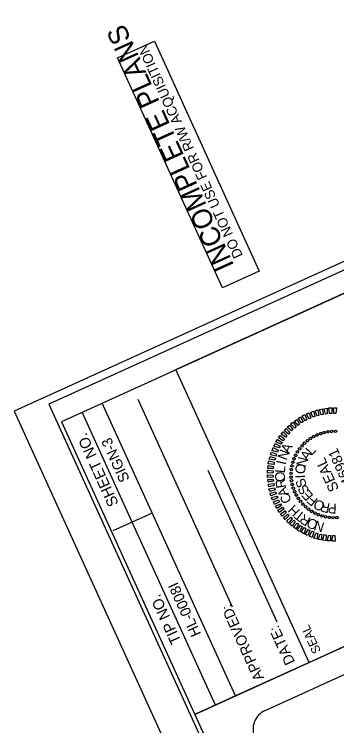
# Model space of a CAD drawing. Extents: x 2096093 to 2099001, y 683546 to 685907.
# Drawn here: x 2097306.8 to 2097494, y 685271.2 to 685684.7 of the extents above; entities that cross this region are included whole.
import ezdxf

# ---------------------------------------------------------------- set-up
doc = ezdxf.new("R2010")
doc.units = 0
for name, color, linetype in [('Default', 7, 'Continuous'), ('Old_Level_10', 7, 'Continuous'), ('Old_Level_2', 7, 'Continuous'), ('Old_Level_4', 7, 'Continuous'), ('Scratch_Level_4', 7, 'Continuous'), ('Sheet Layout Plan Border', 7, 'Continuous'), ('Sheet PE Seal Cell', 7, 'Continuous'), ('Sheet Plan CELL', 7, 'Continuous'), ('Sheet Plot Border Inside CELL', 7, 'Continuous'), ('Sheet Plot Border Outside CELL', 7, 'Continuous'), ('Sheet Sticker Incomplete CELL', 7, 'Continuous'), ('Sheet Title CELL', 7, 'Continuous')]:
    doc.layers.add(name, color=color, linetype=linetype)

msp = doc.modelspace()

# ---------------------------------------------------------------- linework, layer by layer
at = {"layer": 'Default'}
for p, q in [((2097433.54, 685340.15), (2097378.64, 685460.84)), ((2097433.54, 685340.15), (2097378.64, 685460.84)), ((2097435.15, 685288.51), (2097357.76, 685458.68)), ((2097435.15, 685288.51), (2097357.76, 685458.68)), ((2097375.24, 685389.49), (2097346.17, 685453.41)), ((2097375.24, 685389.49), (2097346.17, 685453.41)), ((2097459.39, 685331.39), (2097419.33, 685419.47)), ((2097459.39, 685331.39), (2097419.33, 685419.47)), ((2097386.83, 685394.76), (2097364.11, 685384.43)), ((2097386.83, 685394.76), (2097364.11, 685384.43)), ((2097386.83, 685394.76), (2097364.11, 685384.43)), ((2097386.83, 685394.76), (2097364.11, 685384.43)), ((2097423.56, 685283.23), (2097375.24, 685389.49)), ((2097423.56, 685283.23), (2097375.24, 685389.49)), ((2097435.15, 685288.51), (2097412.45, 685278.18)), ((2097435.15, 685288.51), (2097412.45, 685278.18))]:
    msp.add_line(p, q, dxfattribs=at)
at = {"layer": 'Old_Level_2'}
msp.add_line((2097478.08, 685308.03), (2097435.15, 685288.51), dxfattribs=at)
msp.add_line((2097478.08, 685308.03), (2097435.15, 685288.51), dxfattribs=at)
msp.add_lwpolyline([(2097478.08, 685308.03), (2097400.68, 685478.2), (2097502.07, 685524.32), (2097579.47, 685354.15)], close=True, dxfattribs=at)
msp.add_lwpolyline([(2097478.08, 685308.03), (2097400.68, 685478.2), (2097502.07, 685524.32), (2097579.47, 685354.15)], close=True, dxfattribs=at)
at = {"layer": 'Scratch_Level_4'}
msp.add_lwpolyline([(2097576.74, 685472.35), (2098256.77, 685779.32), (2098363.73, 685544.17), (2098430.06, 685574.34), (2098911.14, 684517.12), (2097955.36, 684082.39), (2097417.22, 685265.53), (2097411.63, 685277.84), (2097412.45, 685278.18), (2097621.75, 685373.38)], close=True, dxfattribs=at)
at = {"layer": 'Sheet Layout Plan Border'}
msp.add_lwpolyline([(2097576.74, 685472.35), (2098256.77, 685779.32), (2098363.73, 685544.17), (2098430.06, 685574.34), (2098911.14, 684517.12), (2097955.36, 684082.39), (2097417.22, 685265.53), (2097411.63, 685277.84), (2097412.45, 685278.18), (2097621.75, 685373.38)], close=True, dxfattribs=at)
at = {"layer": 'Sheet PE Seal Cell'}
for p, q in [((2097482.58, 685440.24), (2097482.58, 685440.24)), ((2097484.64, 685441.01), (2097484.64, 685441.01)), ((2097486.74, 685441.59), (2097486.74, 685441.59)), ((2097488.84, 685442.05), (2097488.84, 685442.05)), ((2097491.04, 685442.28), (2097491.04, 685442.28)), ((2097493.24, 685442.29), (2097493.24, 685442.29)), ((2097476.93, 685436.85), (2097476.93, 685436.85)), ((2097478.76, 685438.12), (2097478.76, 685438.12)), ((2097480.6, 685439.28), (2097480.6, 685439.28)), ((2097472.41, 685432.16), (2097472.41, 685432.16)), ((2097473.77, 685433.87), (2097473.77, 685433.87)), ((2097475.26, 685435.43), (2097475.26, 685435.43)), ((2097470.08, 685428.46), (2097470.08, 685428.46)), ((2097471.16, 685430.32), (2097471.16, 685430.32)), ((2097468.48, 685424.38), (2097468.48, 685424.38)), ((2097469.2, 685426.41), (2097469.2, 685426.41)), ((2097467.58, 685420.07), (2097467.58, 685420.07)), ((2097467.98, 685422.23), (2097467.98, 685422.23)), ((2097467.48, 685417.88), (2097467.48, 685417.88)), ((2097467.49, 685415.69), (2097467.49, 685415.69)), ((2097492.56, 685417.21), (2097492.56, 685417.21)), ((2097467.72, 685413.49), (2097467.72, 685413.49)), ((2097468.18, 685411.39), (2097468.18, 685411.39)), ((2097468.75, 685409.29), (2097468.75, 685409.29)), ((2097469.53, 685407.22), (2097469.53, 685407.22)), ((2097470.48, 685405.24), (2097470.48, 685405.24)), ((2097471.65, 685403.41), (2097471.65, 685403.41)), ((2097472.92, 685401.57), (2097472.92, 685401.57)), ((2097474.34, 685399.91), (2097474.34, 685399.91)), ((2097475.89, 685398.42), (2097475.89, 685398.42)), ((2097477.61, 685397.06), (2097477.61, 685397.06)), ((2097479.44, 685395.81), (2097479.44, 685395.81)), ((2097481.31, 685394.73), (2097481.31, 685394.73)), ((2097483.36, 685393.85), (2097483.36, 685393.85)), ((2097485.39, 685393.13), (2097485.39, 685393.13)), ((2097487.54, 685392.62), (2097487.54, 685392.62)), ((2097489.7, 685392.23), (2097489.7, 685392.23)), ((2097491.88, 685392.13), (2097491.88, 685392.13))]:
    msp.add_line(p, q, dxfattribs=at)
for points in [[(2097477.86, 685449.52), (2097476.38, 685452.42), (2097477.93, 685453.12), (2097478.96, 685450.02)], [(2097480.16, 685450.51), (2097478.9, 685453.51), (2097480.45, 685454.1), (2097481.29, 685450.92)], [(2097482.45, 685451.28), (2097481.4, 685454.31), (2097483.03, 685454.84), (2097483.64, 685451.55)], [(2097484.93, 685451.97), (2097484.01, 685454.96), (2097485.71, 685455.34), (2097486.06, 685452.04)], [(2097487.39, 685452.37), (2097486.7, 685455.46), (2097488.34, 685455.83), (2097488.51, 685452.44)], [(2097489.88, 685452.68), (2097489.42, 685455.88), (2097491.1, 685455.93), (2097491.07, 685452.61)], [(2097492.3, 685452.68), (2097492.06, 685455.98), (2097493.78, 685455.94), (2097493.51, 685452.68)], [(2097471.55, 685445.77), (2097469.38, 685448.24), (2097470.8, 685449.22), (2097472.38, 685446.48)], [(2097473.55, 685447.17), (2097471.56, 685449.84), (2097473.05, 685450.68), (2097474.56, 685447.85)], [(2097475.61, 685448.44), (2097473.9, 685451.23), (2097475.4, 685452.03), (2097476.66, 685449.03)], [(2097467.76, 685442.51), (2097465.31, 685444.75), (2097466.5, 685445.89), (2097468.51, 685443.4)], [(2097469.61, 685444.23), (2097467.24, 685446.67), (2097468.62, 685447.62), (2097470.42, 685444.98)], [(2097464.45, 685438.92), (2097461.7, 685440.74), (2097462.84, 685441.97), (2097465.07, 685439.86)], [(2097465.99, 685440.72), (2097463.41, 685442.78), (2097464.59, 685444.03), (2097466.79, 685441.63)], [(2097461.66, 685434.79), (2097458.73, 685436.15), (2097459.66, 685437.62), (2097462.27, 685435.73)], [(2097462.99, 685436.82), (2097460.16, 685438.45), (2097461.13, 685439.93), (2097463.61, 685437.87)], [(2097459.59, 685430.28), (2097456.56, 685431.26), (2097457.16, 685432.85), (2097460.01, 685431.29)], [(2097460.5, 685432.62), (2097457.5, 685433.78), (2097458.3, 685435.29), (2097461.12, 685433.67)], [(2097458.12, 685425.54), (2097454.85, 685426.09), (2097455.31, 685427.73), (2097458.36, 685426.7)], [(2097458.74, 685427.92), (2097455.53, 685428.71), (2097456.12, 685430.29), (2097459.03, 685429.09)], [(2097457.6, 685423.06), (2097454.24, 685423.45), (2097454.65, 685425.07), (2097457.69, 685424.31)], [(2097457.09, 685418.15), (2097453.88, 685418.07), (2097453.88, 685419.77), (2097457.13, 685419.38)], [(2097457.18, 685420.72), (2097454.03, 685420.77), (2097454.18, 685422.49), (2097457.33, 685421.84)], [(2097457.15, 685415.71), (2097453.81, 685415.45), (2097453.78, 685416.98), (2097456.99, 685416.9)], [(2097457.26, 685413.29), (2097454.13, 685412.69), (2097453.95, 685414.31), (2097457.15, 685414.39)], [(2097457.67, 685410.84), (2097454.5, 685409.95), (2097454.16, 685411.66), (2097457.46, 685411.9)], [(2097458.22, 685408.29), (2097455.12, 685407.37), (2097454.67, 685408.98), (2097457.86, 685409.44)], [(2097458.85, 685405.94), (2097455.81, 685404.77), (2097455.4, 685406.4), (2097458.54, 685407.11)], [(2097459.75, 685403.6), (2097456.79, 685402.26), (2097456.15, 685403.78), (2097459.3, 685404.71)], [(2097460.7, 685401.4), (2097457.84, 685399.82), (2097457.21, 685401.34), (2097460.25, 685402.51)], [(2097461.96, 685399.22), (2097459.28, 685397.4), (2097458.39, 685398.86), (2097461.33, 685400.25)], [(2097463.23, 685397.16), (2097460.65, 685395.11), (2097459.83, 685396.55), (2097462.59, 685398.19)], [(2097464.72, 685395.21), (2097462.29, 685392.95), (2097461.27, 685394.35), (2097464.06, 685396.06)], [(2097466.31, 685393.29), (2097464.05, 685391), (2097463, 685392.23), (2097465.55, 685394.1)], [(2097468.05, 685391.39), (2097465.95, 685389.01), (2097464.78, 685390.12), (2097467.26, 685392.4)], [(2097469.92, 685389.82), (2097468.03, 685387.21), (2097466.75, 685388.33), (2097469.05, 685390.64)], [(2097471.9, 685388.36), (2097470.21, 685385.56), (2097468.84, 685386.64), (2097470.96, 685388.98)], [(2097473.95, 685386.88), (2097472.39, 685384.14), (2097470.99, 685384.93), (2097472.95, 685387.63)], [(2097476.1, 685385.77), (2097474.8, 685382.82), (2097473.29, 685383.61), (2097475.11, 685386.37)], [(2097478.34, 685384.59), (2097477.25, 685381.68), (2097475.66, 685382.27), (2097477.31, 685385.17)], [(2097480.61, 685383.81), (2097479.8, 685380.64), (2097478.24, 685381.31), (2097479.55, 685384.21)], [(2097483.07, 685383.01), (2097482.37, 685379.83), (2097480.73, 685380.3), (2097481.96, 685383.27)], [(2097485.42, 685382.43), (2097484.99, 685379.27), (2097483.28, 685379.53), (2097484.28, 685382.63)], [(2097487.86, 685381.89), (2097487.65, 685378.72), (2097485.97, 685379.05), (2097486.71, 685382.25)], [(2097490.31, 685381.69), (2097490.36, 685378.58), (2097488.63, 685378.62), (2097489.2, 685381.84)], [(2097492.82, 685381.73), (2097493.06, 685378.43), (2097491.34, 685378.47), (2097491.61, 685381.73)]]:
    msp.add_lwpolyline(points, close=True, dxfattribs=at)
for centre, major_axis in [((2097480.61, 685439.26), (-0.343, 0.633)), ((2097482.58, 685440.21), (-0.287, 0.66)), ((2097484.62, 685441), (-0.228, 0.683)), ((2097486.72, 685441.6), (-0.168, 0.7)), ((2097488.87, 685442.01), (-0.106, 0.712)), ((2097491.05, 685442.24), (-0.043, 0.719)), ((2097493.24, 685442.28), (0.019, 0.72)), ((2097475.31, 685435.41), (-0.495, 0.523)), ((2097476.96, 685436.85), (-0.448, 0.564)), ((2097478.73, 685438.13), (-0.397, 0.601)), ((2097472.41, 685432.14), (-0.578, 0.429)), ((2097473.79, 685433.84), (-0.539, 0.477)), ((2097470.12, 685428.41), (-0.644, 0.322)), ((2097471.19, 685430.33), (-0.614, 0.377)), ((2097468.52, 685424.35), (-0.69, 0.205)), ((2097469.23, 685426.42), (-0.67, 0.264)), ((2097467.64, 685420.06), (-0.715, 0.082)), ((2097467.99, 685422.22), (-0.705, 0.144)), ((2097467.49, 685417.88), (-0.72, 0.019)), ((2097467.53, 685415.69), (-0.719, -0.043)), ((2097467.75, 685413.52), (-0.712, -0.106)), ((2097468.17, 685411.37), (-0.7, -0.168)), ((2097468.77, 685409.27), (-0.683, -0.228)), ((2097469.55, 685407.22), (-0.66, -0.287)), ((2097470.51, 685405.26), (-0.633, -0.343)), ((2097471.64, 685403.38), (-0.601, -0.397)), ((2097472.92, 685401.61), (-0.564, -0.448)), ((2097474.36, 685399.96), (-0.523, -0.495)), ((2097475.93, 685398.43), (-0.477, -0.539)), ((2097477.63, 685397.06), (-0.429, -0.578)), ((2097479.44, 685395.83), (-0.377, -0.614)), ((2097481.35, 685394.77), (-0.322, -0.644)), ((2097483.35, 685393.88), (-0.264, -0.67)), ((2097485.42, 685393.16), (-0.205, -0.69)), ((2097487.54, 685392.63), (-0.144, -0.705)), ((2097489.7, 685392.29), (-0.082, -0.715)), ((2097491.89, 685392.14), (-0.019, -0.72)), ((2097494.07, 685392.17), (0.043, -0.719))]:
    msp.add_ellipse(centre, major_axis=major_axis, ratio=0.999708, dxfattribs=at)
at = {"layer": 'Sheet Plan CELL'}
msp.add_lwpolyline([(2097334.31, 685447.82), (2097955.36, 684082.39), (2098911.14, 684517.12), (2098290.1, 685882.52)], close=True, dxfattribs=at)
msp.add_lwpolyline([(2097334.31, 685447.82), (2097955.36, 684082.39), (2098911.14, 684517.12), (2098290.1, 685882.52)], close=True, dxfattribs=at)
at = {"layer": 'Sheet Plot Border Inside CELL'}
msp.add_lwpolyline([(2098976.98, 684378.44), (2098287.2, 685894.93), (2097326.88, 685458.15), (2098016.65, 683941.64)], close=True, dxfattribs=at)
msp.add_lwpolyline([(2098976.98, 684378.44), (2098287.2, 685894.93), (2097326.88, 685458.15), (2098016.65, 683941.64)], close=True, dxfattribs=at)
at = {"layer": 'Sheet Plot Border Outside CELL'}
msp.add_lwpolyline([(2099000.57, 684374.89), (2098303.55, 685907.32), (2097306.81, 685453.96), (2098003.83, 683921.53)], close=True, dxfattribs=at)
msp.add_lwpolyline([(2099000.57, 684374.89), (2098303.55, 685907.32), (2097306.81, 685453.96), (2098003.83, 683921.53)], close=True, dxfattribs=at)
at = {"layer": 'Sheet Sticker Incomplete CELL'}
msp.add_lwpolyline([(2097449.01, 685535.35), (2097427.62, 685525.62), (2097366.76, 685659.42), (2097388.15, 685669.15)], close=True, dxfattribs=at)
msp.add_lwpolyline([(2097449.01, 685535.35), (2097427.62, 685525.62), (2097366.76, 685659.42), (2097388.15, 685669.15)], close=True, dxfattribs=at)
at = {"layer": 'Sheet Title CELL'}
msp.add_line((2097452.42, 685280.04), (2097525.26, 685313.17), dxfattribs=at)
msp.add_arc((2097457.39, 685269.12), 12, 114.458, 204.458, dxfattribs=at)

# ---------------------------------------------------------------- texts
at = {"layer": 'Default'}
for s, height, p in [('SHEET NO.', 6.356, (2097367.53, 685400.29)), ('SHEET NO.', 6.356, (2097367.53, 685400.29)), ('SIGN-3', 6.108, (2097373.96, 685414.42)), ('HL-0008I', 6.108, (2097415.37, 685324.6)), ('TIP NO.', 6.356, (2097403.91, 685320.28)), ('TIP NO.', 6.356, (2097403.91, 685320.28))]:
    msp.add_text(s, height=height, rotation=114.4529, dxfattribs=at).set_placement(p)
at = {"layer": 'Old_Level_10'}
msp.add_text('SEAL', height=5.093, rotation=114.4529, dxfattribs=at).set_placement((2097484.94, 685314.48))
msp.add_text('SEAL', height=5.093, rotation=114.4529, dxfattribs=at).set_placement((2097484.94, 685314.48))
at = {"layer": 'Old_Level_4'}
for s, p in [('APPROVED:', (2097451.97, 685299)), ('APPROVED:', (2097451.97, 685299)), ('DATE:', (2097469.91, 685308.17)), ('DATE:', (2097469.91, 685308.17))]:
    msp.add_text(s, height=6.108, rotation=114.4529, dxfattribs=at).set_placement(p)
at = {"layer": 'Sheet PE Seal Cell'}
for s, height, rotation, p in [('N', 5.78, 70.2769, (2097464.9, 685425.12)), ('A', 5.77, 63.0751, (2097466.37, 685429.02)), ('L', 5.7, 46.8588, (2097479.47, 685428)), ('046981', 5.998, 114.458, (2097505.22, 685408.71)), ('A', 5.75, 56.2182, (2097477.13, 685424.8)), ('I', 5.78, 77.4781, (2097464.38, 685422.52)), ('N', 5.78, 74.9346, (2097475.95, 685421.13)), ('SEAL', 5.998, 114.458, (2097495.43, 685408.85)), ('L', 5.75, 84.6789, (2097463.88, 685417.84)), ('O', 5.76, 84.2915, (2097475.51, 685417.25)), ('O', 5.72, 91.8791, (2097464.01, 685413.07)), ('I', 5.71, 93.6476, (2097475.7, 685415.14)), ('R', 5.68, 99.0791, (2097464.72, 685409.71)), ('S', 5.64, 112.3584, (2097476.85, 685410.94)), ('S', 5.65, 121.7136, (2097478.38, 685407.68)), ('A', 5.64, 113.4783, (2097466.27, 685405.8)), ('E', 5.69, 131.069, (2097480.77, 685404.98)), ('C', 5.65, 120.6779, (2097468.18, 685402.33)), ('F', 5.74, 140.425, (2097483.46, 685402.68)), ('H', 5.71, 135.0775, (2097473.15, 685396.24)), ('O', 5.78, 159.1392, (2097487.51, 685400.9)), ('R', 5.76, 168.4976, (2097490.46, 685400.32)), ('P', 5.72, 177.8569, (2097494.04, 685400.19)), ('T', 5.75, 142.2778, (2097476, 685393.96)), ('R', 5.77, 149.4785, (2097479.41, 685391.78)), ('O', 5.78, 156.6797, (2097483.66, 685389.92)), ('N', 5.78, 163.8815, (2097487.25, 685389.03))]:
    msp.add_text(s, height=height, rotation=rotation, dxfattribs=at).set_placement(p)
at = {"layer": 'Sheet Sticker Incomplete CELL'}
for s, height, p in [('INCOMPLETE PLANS', 11.52, (2097434.65, 685538.65)), ('INCOMPLETE PLANS', 11.52, (2097434.65, 685538.65)), ('DO NOT USE FOR R/W ACQUISITION', 5.76, (2097439.64, 685544.48)), ('DO NOT USE FOR R/W ACQUISITION', 5.76, (2097439.64, 685544.48))]:
    msp.add_text(s, height=height, rotation=114.458, dxfattribs=at).set_placement(p)

doc.saveas('drawing.dxf')
